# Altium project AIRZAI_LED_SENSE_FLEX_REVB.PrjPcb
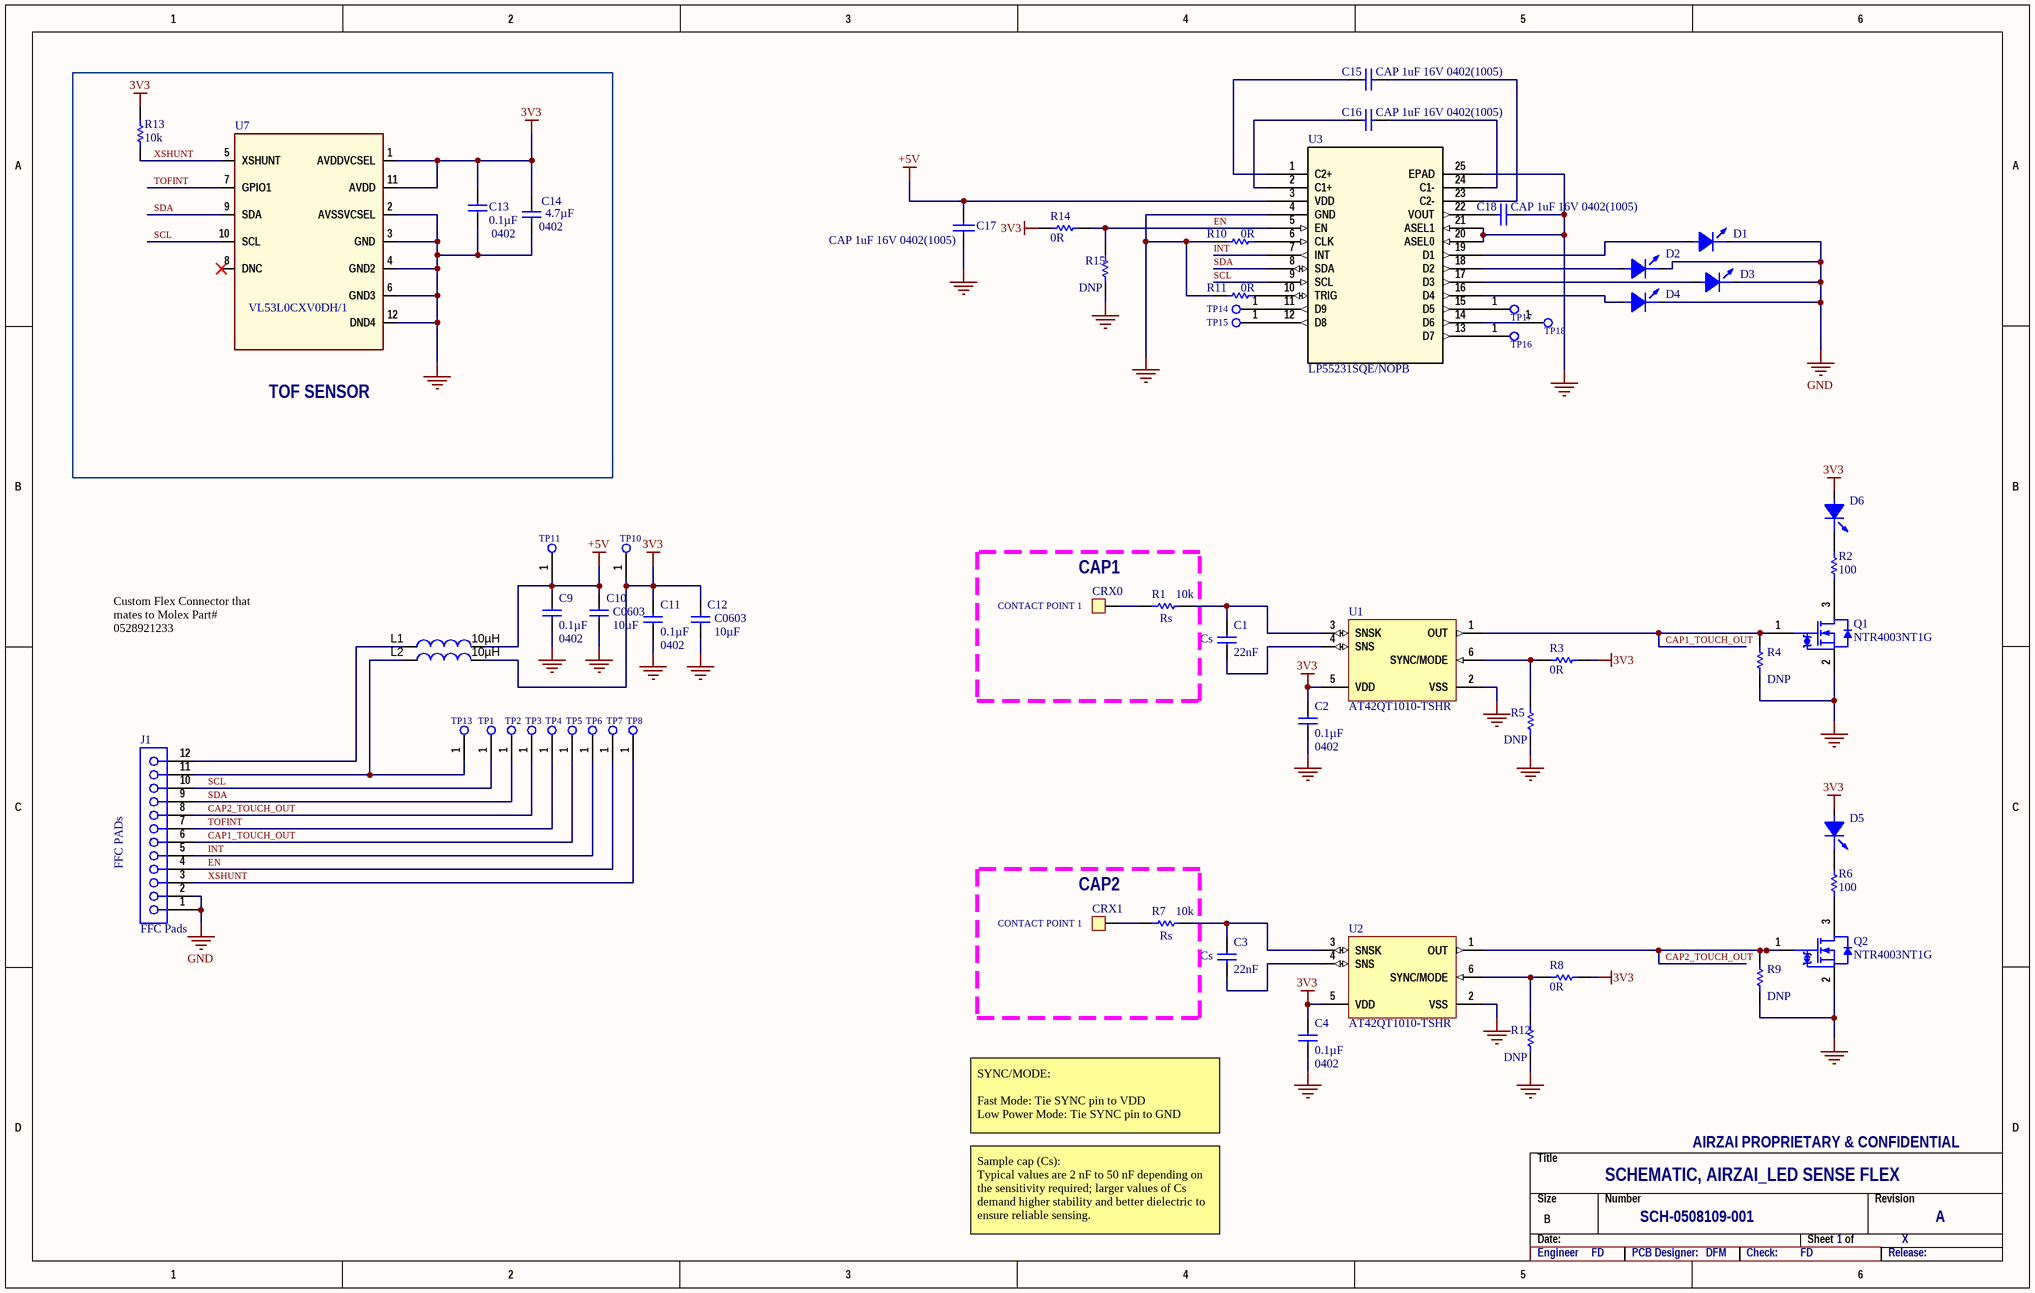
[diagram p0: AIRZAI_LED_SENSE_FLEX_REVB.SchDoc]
1 sheet, 62 parts. Net scope: global (net labels, ports and power ports of the same name join across sheets).
Board file: AIRZAI_LED_SENSE_FLEX_REVB.PcbDoc

## Sheet AIRZAI_LED_SENSE_FLEX_REVB.SchDoc
size B

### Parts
C1  22nF  [0402CAP]
C2  0.1µF  Footprint: 0402  [0402CAP]
C3  22nF  [0402CAP]
C4  0.1µF  Footprint: 0402  [0402CAP]
C9  0.1µF  Footprint: 0402  [0402CAP]
C10  10µF  Footprint: C0603  [0603]
C11  0.1µF  Footprint: 0402  [0402CAP]
C12  10µF  Footprint: C0603  [0603]
C13  0.1µF  Footprint: 0402  [0402CAP]
C14  4.7µF  Footprint: 0402  [0603]
C15  CAP 1uF 16V 0402(1005)  [CAPC0402(1005)60_M]
C16  CAP 1uF 16V 0402(1005)  [CAPC0402(1005)60_M]
C17  CAP 1uF 16V 0402(1005)  [CAPC0402(1005)60_M]
C18  CAP 1uF 16V 0402(1005)  [CAPC0402(1005)60_M]
CRX0  CONTACT POINT 1  [CONTACT_POINT_1CM _SQ]
CRX1  CONTACT POINT 1  [CONTACT_POINT_1CM _SQ]
D1  WHITE  [LED1206_LTW-C230DS]  (value not drawn)
D2  WHITE  [LED1206_LTW-C230DS]  (value not drawn)
D3  WHITE  [LED1206_LTW-C230DS]  (value not drawn)
D4  WHITE  [LED1206_LTW-C230DS]  (value not drawn)
D5  WHITE  [LED1206_LTW-C230DS]  (value not drawn)
D6  WHITE  [LED1206_LTW-C230DS]  (value not drawn)
J1  FFC Pads  [FFC_Pads]
L1  ValueDisplayed: 10µH  [0805]  (hidden comment: CB2012T100KR)
L2  ValueDisplayed: 10µH  [0805]  (hidden comment: CB2012T100KR)
Q1  NTR4003NT1G  [SOT-23-3-NTR4003NT1G]
Q2  NTR4003NT1G  [SOT-23-3-NTR4003NT1G]
R1  value 10k  [0402]  (hidden comment: 10k 0402(1005))
R2  value 100  [0402]  (hidden comment: 100R 0402(1005))
R3  value 0R  [0402]  (hidden comment: Jumper 0402(1005))
R4  value DNP  [0402]  (hidden comment: DNP 0402(1005))
R5  value DNP  [0402]  (hidden comment: DNP 0402(1005))
R6  value 100  [0402]  (hidden comment: 100R 0402(1005))
R7  value 10k  [0402]  (hidden comment: 10k 0402(1005))
R8  value 0R  [0402]  (hidden comment: Jumper 0402(1005))
R9  value DNP  [0402]  (hidden comment: DNP 0402(1005))
R10  value 0R  [0402]  (hidden comment: Jumper 0402(1005))
R11  value 0R  [0402]  (hidden comment: Jumper 0402(1005))
R12  value DNP  [0402]  (hidden comment: DNP 0402(1005))
R13  value 10k  [0402]  (hidden comment: 10k 0402(1005))
R14  value 0R  [0402]  (hidden comment: Jumper 0402(1005))
R15  value DNP  [0402]  (hidden comment: DNP 0402(1005))
TP1  Test Point  [TP_0.9MM]  (value not drawn)
TP2  Test Point  [TP_0.9MM]  (value not drawn)
TP3  Test Point  [TP_0.9MM]  (value not drawn)
TP4  Test Point  [TP_0.9MM]  (value not drawn)
TP5  Test Point  [TP_0.9MM]  (value not drawn)
TP6  Test Point  [TP_0.9MM]  (value not drawn)
TP7  Test Point  [TP_0.9MM]  (value not drawn)
TP8  Test Point  [TP_0.9MM]  (value not drawn)
TP10  Test Point  [TP_0.9MM]  (value not drawn)
TP11  Test Point  [TP_0.9MM]  (value not drawn)
TP13  Test Point  [TP_0.9MM]  (value not drawn)
TP14  Test Point  [TP_0.9MM]  (value not drawn)
TP15  Test Point  [TP_0.9MM]  (value not drawn)
TP16  Test Point  [TP_0.9MM]  (value not drawn)
TP17  Test Point  [TP_0.9MM]  (value not drawn)
TP18  Test Point  [TP_0.9MM]  (value not drawn)
U1  AT42QT1010-TSHR  [SOT-23-6-AT42QT1010-TSHR]
U2  AT42QT1010-TSHR  [SOT-23-6-AT42QT1010-TSHR]
U3  LP55231SQE/NOPB  [WQFN-24-LP55231SQE/NOPB]
U7  VL53L0CXV0DH/1  [VL53L0X]

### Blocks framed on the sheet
TOF SENSOR: C13 C14 R13 U7
CAP1: CRX0 R1
CAP2: CRX1 R7

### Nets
3V3: C2.1 C4.1 C11.1 C12.1 C13.1 C14.2 D5.2(ANODE) D6.2(ANODE) L2.2 R3.2 R8.2 R13.1 R14.1 TP10.1 U1.5(VDD) U2.5(VDD) U7.1(AVDDVCSEL) U7.11(AVDD)
+5V: C9.1 C10.1 C17.2 L1.2 TP11.1 U3.3(VDD)
GND: C2.2 C4.2 C9.2 C10.2 C11.2 C12.2 C13.2 C14.1 C17.1 C18.2 D1.1(CATHODE) D2.1(CATHODE) D3.1(CATHODE) D4.1(CATHODE) J1.1 J1.2 Q1.2(S) Q2.2(S) R4.2 R5.2 R9.2 R10.1 R11.1 R12.2 R15.2 U1.2(VSS) U2.2(VSS) U3.4(GND) U3.20(ASEL0) U3.21(ASEL1) U3.25(EPAD) U7.2(AVSSVCSEL) U7.3(GND) U7.4(GND2) U7.6(GND3) U7.12(DND4)
CAP1_TOUCH_OUT: J1.6 Q1.1(G) R4.1 TP5.1 U1.1(OUT)
CAP2_TOUCH_OUT: J1.8 Q2.1(G) R9.1 TP3.1 U2.1(OUT)
EN: J1.4 R14.2 R15.1 TP7.1 U3.5(EN)
INT: J1.5 TP6.1 U3.7(INT)
SCL: J1.10 TP1.1 U3.9(SCL) U7.10(SCL)
SDA: J1.9 TP2.1 U3.8(SDA) U7.9(SDA)
TOFINT: J1.7 TP4.1 U7.7(GPIO1)
XSHUNT: J1.3 R13.2 TP8.1 U7.5(XSHUNT)
NetC1_1: C1.1 R1.1 U1.3(SNSK)
NetC1_2: C1.2 U1.4(SNS)
NetC3_1: C3.1 R7.1 U2.3(SNSK)
NetC3_2: C3.2 U2.4(SNS)
NetC15_1: C15.1 U3.1(C2+)
NetC15_2: C15.2 U3.23(C2-)
NetC16_1: C16.1 U3.2(C1+)
NetC16_2: C16.2 U3.24(C1-)
NetC18_1: C18.1 U3.22(VOUT)
NetCRX0_1: CRX0.1 R1.2
NetCRX1_1: CRX1.1 R7.2
NetD1_2: D1.2(ANODE) U3.19(D1)
NetD2_2: D2.2(ANODE) U3.18(D2)
NetD3_2: D3.2(ANODE) U3.17(D3)
NetD4_2: D4.2(ANODE) U3.16(D4)
NetD5_1: D5.1(CATHODE) R6.2
NetD6_1: D6.1(CATHODE) R2.2
NetJ1_11: J1.11 L2.1 TP13.1
NetJ1_12: J1.12 L1.1
NetQ1_3: Q1.3(D) R2.1
NetQ2_3: Q2.3(D) R6.1
NetR3_1: R3.1 R5.1 U1.6(SYNC/MODE)
NetR8_1: R8.1 R12.1 U2.6(SYNC/MODE)
NetR10_2: R10.2 U3.6(CLK)
NetR11_2: R11.2 U3.10(TRIG)
NetTP14_1: TP14.1 U3.11(D9)
NetTP15_1: TP15.1 U3.12(D8)
NetTP16_1: TP16.1 U3.13(D7)
NetTP17_1: TP17.1 U3.15(D5)
NetTP18_1: TP18.1 U3.14(D6)

Not connected (* = marked no-connect by the designer): U7 8(DNC)*

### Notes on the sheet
- (near R1) Rs
- (near C1) Cs
- Custom Flex Connector that mates to Molex Part# 0528921233
- (near J1) FFC PADs
- (near R7) Rs
- (near C3) Cs
- SYNC/MODE:
  Fast Mode: Tie SYNC pin to VDD
  Low Power Mode: Tie SYNC pin to GND
- SCHEMATIC, AIRZAI_LED SENSE FLEX
- AIRZAI PROPRIETARY & CONFIDENTIAL
- Sample cap (Cs):
  Typical values are 2 nF to 50 nF depending on the sensitivity required; larger values of Cs demand higher stability and better dielectric to ensure reliable sensing.
- SCH-0508109-001
- 1
- X
- A
- Engineer
- FD
- PCB Designer:
- DFM
- Check:
- Release:

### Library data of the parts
C1 C3 = C0402-100n: Capacitor, X7R, ±10%; Manufacturer: TDK; Manufacturer Part Number: CGA2B2X7R1E223K050BA; Voltage Rating (DC): 25V
C2 C4 C9 C11 C13 = C0402-100n: Capacitor, X7R, ±10%; Manufacturer: TDK; Manufacturer Part Number: C1005X7R1C104K; Note: 16V ±10% X7R; Case-Metric: 1005; Rated Voltage: 16 V; Tolerance: Â±20%
C10 C12 = C0402-100n: Capacitor, X7R, ±10%; Manufacturer: MURATA; Manufacturer Part Number: GRM188R60J106ME47D; Note: 6.3volts X5R 20%; Case-Metric: 1608; Rated Voltage: 6.3 V; Tolerance: Â±20%
C14 = C0603-1µ0 X7R: Capacitor, X7R, ±10%; Manufacturer: TDK; Manufacturer Part Number: C1005X5R0J475M; Case-Metric: 1005; Note: 6.3volts X5R 20%; Rated Voltage: 6.3 V; Tolerance: Â±20%
C15-C18 = CAP: CAP 1uF 16V ±10% 0402 (1005 Metric) Thickness 0.6mm SMD; Manufacturer: Taiyo Yuden; Manufacturer Part Number: JMK105C6105KV-F; Case-EIA: 0402; Rated Voltage: 6.3 V; Tolerance: Â±10%; Case-Metric: 1005; Note: CAP CER 1UF 6.3V X6S 0402
CRX0 CRX1 = WIRE_POINT
D1-D6 = LED_LTW-C230DS: Manufacturer: LITEON; Note: REVERSE MOUNT CHIP LED; Case-EIA: 1206; Case-Metric: 3216
J1 = FFC_PADS: 0.5 mm Pitch FFC Pads; Note: DNP
L1 L2 = CB2012T100KR: Inductor, 10 µH, 0.5A, 0.65 ohm, SMD; Manufacturer: Taiyo Yuden; Value: 10uH; Core Material: Ferrite; Current Rating: 520mA; Saturation Current: 200mA; Tolerance: 10%; Shielding: Unshielded; Self Resonant Frequency: 32MHz; DC Resistance (DCR): 500mR; Test Frequency: 2.52MHz
Q1 Q2 = NTR4003NT1G: N-Channel 30V 500mA (Ta) 690mW (Ta) Surface Mount SOT-23-3 (TO-236); Manufacturer: ON Semiconductor; Nominal Vgs: 1.4V; Rise Time: 47.9ns; Input Capacitance: 21pF; Number of Elements: 1; Rds On Max: 1.5R; Drain to Source Resistance: 1R; Turn-Off Delay Time: 65.1ns; Turn-On Delay Time: 16.7ns; Element Configuration: Single; Gate to Source Voltage (Vgs): 20V
R1 R7 R13 = RES: 10k 0.063W 1% 0402 (1005 Metric)  SMD; Manufacturer: Yageo; Manufacturer Part Number: RC0402FR-0710KL; Tolerance: None; Case-Metric: 1005; Note: RES SMD 10K OHM 1% 1/16W 0402
R2 R6 = RES: 100 0.063W 1% 0402 (1005 Metric)  SMD; Manufacturer: Yageo; Manufacturer Part Number: RC0402FR-07100RL; Tolerance: None; Case-Metric: 1005; Note: 0.1W JUMPER
R3 R8 R10 R11 R14 = RES: Jumper 0402 (1005 Metric); Manufacturer: Panasonic; Manufacturer Part Number: ERJ-2GE0R00X; Tolerance: None; Case-Metric: 1005; Note: 0.1W JUMPER
R4 R5 R9 R12 R15 = RES: DNP; Tolerance: None; Case-Metric: 1005; Power: 0.0625 W
U1 U2 = AT42QT1010-TSHR: One-channel Touch Sensor IC with Reset Timer, -40° to +85° C, 6-pin SOT23
U3 = LP55231SQE/NOPB: Imported; Manufacturer: TI; Vendor: Texas Instruments; Built_By: EMA_UL_Team; Value: IC LED DRIVER RGLTR DIM 24WQFN; C: Copyright (C) 2016 Accelerated Designs. All rights reserved; Case-EIA: 24-WQFN; Tolerance: None
U7 = VL53L0X: Manufacturer: ST; Note: SENSOR LASER DISTANCE TOF 2M; Case-EIA: LGA12; Tolerance: None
